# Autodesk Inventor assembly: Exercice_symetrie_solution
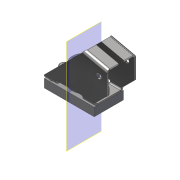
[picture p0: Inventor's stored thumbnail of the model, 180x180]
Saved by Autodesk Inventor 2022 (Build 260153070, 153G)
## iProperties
Created: 2018-06
Part Number: Exercice_symetrie_solution
Material: Générique
Document SubType Name: Assembly
Designer: Fabian Perrée
Mass: 105.136 g
Surface Area: 173.547 cm^2
Volume: 19.7524 cm^3
Density: 5.32267 g/cm^3
Author: Fabian Perrée
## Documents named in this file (5)
- C:\Users\Fabian\Google Drive\01_Giup\01_Clients\07_ENI\Manuscrit\Fichiers_exercice\Chapitre_06\Exercice_symétrie\Exercice_symetrie_solution.iam
- C:\Users\Fabian\Google Drive\01_Giup\01_Clients\07_ENI\Manuscrit\Fichiers_exercice\Chapitre_06\Exercice_symétrie\Composants\Etrier_tole.ipt
- C:\Users\Fabian\Google Drive\01_Giup\01_Clients\07_ENI\Manuscrit\Fichiers_exercice\Chapitre_06\Exercice_symétrie\Composants\ISO 4762 - M5 x 8ISO_Custom.ipt
- C:\Users\Fabian\Google Drive\01_Giup\01_Clients\07_ENI\Manuscrit\Fichiers_exercice\Chapitre_06\Exercice_symétrie\Composants\Chapeau_capteur.ipt
- C:\Users\Fabian\Google Drive\01_Giup\01_Clients\07_ENI\Manuscrit\Fichiers_exercice\Chapitre_06\Exercice_symétrie\Composants\Bille_18.ipt
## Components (5 placed, 5 different names)
1. Etrier_tole:1 — Logement:3, Logement:4
2. Chapeau_capteur:1 — Logement:3, Logement:4
3. Bille_18:1
4. ISO 4762 M5 x 8_Custom:2
5. ISO 4762 M5 x 8:3
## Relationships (2: Insert 2)
- Logement:3 [Insert]: Etrier_tole:1 ↔ Chapeau_capteur:1
- Logement:4 [Insert]: Etrier_tole:1 ↔ Chapeau_capteur:1
